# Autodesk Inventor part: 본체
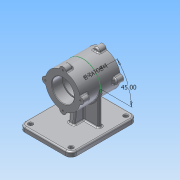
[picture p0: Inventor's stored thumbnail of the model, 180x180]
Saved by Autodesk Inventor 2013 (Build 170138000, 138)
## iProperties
Created: 2015-12
Part Number: 본체
Material: 알루미늄 6061
Document SubType Name: Modeling
Designer: user-11
Density: 2.71 g/cm^3
Mass: 1174.47 g
Surface Area: 817.122 cm^2
Volume: 433.385 cm^3
Author: user-11
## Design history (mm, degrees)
sketch "스케치1"
  geometry: C1 r 37 at (0, 0); 1 further point
  constraints: 1 centre point, 1 coincident
  dimensions: "d0" = 74 diameter of C1
extrude "돌출1" new body sketch "스케치1" stored distance "d2" = 85; taper "d3" = 0 deg
sketch "스케치2"
  geometry: C1 r 7 at (0, 37); 1 further point
  constraints: 2 vertical alignment, 1 centre point, 1 other
  dimensions: "d4" = 14 diameter of C1
extrude "돌출2" join sketch "스케치2" distance "d7" = 15; taper "d8" = 0 deg
node "작업 평면1"
node "작업 평면2"
sketch "스케치4"
  geometry: L1 (55, 80)-(-55, 80); L2 (-55, 80)-(-55, -60); L3 (-55, -60)-(55, -60); L4 (55, -60)-(55, 80); 2 further points
  constraints: 8 end point, 2 parallel, 1 horizontal, 1 midpoint, 1 perpendicular, 1 vertical alignment
  dimensions: "d14" = 55 distance from line of L4 point (0, 0); "d15" = 80 distance from line of L1 point (0, 0); "d16" = 140 distance of L3.end L1.start
extrude "돌출4" join sketch "스케치4" distance "d17" = 10; taper "d18" = 0 deg
sketch "스케치5"
  geometry: L1 (-55, -80)-(55, -80) reference; L2 (-55, 60)-(-55, -80) reference; C1 r 4 at (-43, -68); 1 further point
  constraints: 1 centre point
  dimensions: "d19" = 12 distance from line of L1 C1.centre; "d20" = 12 distance from line of C1.centre L2; "d21" = 8 diameter of C1
extrude "돌출5" cut sketch "스케치5" distance "d22" = 10; taper "d23" = 0 deg
sketch "스케치7"
  geometry: L1 (-55, -80)-(55, -80) reference; L2 (55, 60)-(-55, 60) reference; L3 (-6, 4)-(6, 4); L4 (6, 4)-(6, -4); L5 (6, -4)-(-6, -4); L6 (-6, -4)-(-6, 4); 3 further points
  constraints: 8 end point, 2 midpoint, 2 parallel, 1 horizontal, 1 perpendicular, 1 vertical alignment
  dimensions: "d30" = 8 distance of L5.end L3.start; "d32" = 12 distance of L3.start L3.end; "d33" = 84 distance between parallel lines of L1 L3
extrude "돌출6" join sketch "스케치7" stored distance "d34" = 10; taper "d35" = 0 deg
sketch "스케치8"
  geometry: L1 (-70, -60)-(-70, 80) reference; L2 (-37, -42.5)-(-37, 42.5) reference; L3 (-70, -25)-(-37, -20.948); L4 (-36.51, -4)-(-36.51, 4) reference; L5 (-70, -4)-(-36.51, -4) reference; L6 (-70, 4)-(-70, -4) reference; L7 (-70, 4)-(-36.51, 4) reference; 1 further point
  constraints: 2 end point, 2 point on line
  dimensions: "d36" = 29 distance of L3.start L6.start; "d37" = 97 deg angle of L3 L1
feature "리브1" sketch "스케치8" dims "d38" = 1, "d39" = 12, "d40" = 0, "d41" = 0, "d42" = 1, "d43" = 1
node "작업 평면3"
sketch "스케치9"
  geometry: L1 (-6, -70)-(6, -70) reference; L2 (55, -70)-(-55, -70) reference; L3 (-37, -70)-(-37, 0); 2 further points
  constraints: 2 end point, 1 horizontal alignment, 1 point on line, 1 vertical, 1 other
  dimensions: "d45" = 37 distance from line of L3 point (0, 0)
feature "리브2" sketch "스케치9" dims "d46" = 1, "d47" = 8, "d48" = 0, "d49" = 0, "d50" = 1, "d51" = 1
sketch "스케치10"
  geometry: C1 r 23.5 at (0, 0); A1 r 37 centre (0, 0) between (-6.969, 36.338) and (6.969, 36.338) reference
  constraints: 1 centre point, 1 coincident
  dimensions: "d52" = 47 diameter of C1
extrude "돌출7" cut sketch "스케치10" distance "d54" = 22; taper "d55" = 0 deg
sketch "스케치11"
  geometry: C1 r 23.5 at (0, 0) reference; C2 r 21 at (0, 0)
  constraints: 1 centre point, 1 coincident
  dimensions: "d56" = 42 diameter of C2
extrude "돌출8" cut sketch "스케치11" distance "d58" = 41; taper "d59" = 0 deg
sketch "스케치12"
  geometry: L1 (37, 0)-(0, 0); L2 (0, 0)-(26.163, 26.163); A1 r 37 centre (0, 0) between (37, 0) and (26.163, 26.163) reference; 1 further point
  constraints: 4 end point, 2 point on circle, 1 horizontal
  dimensions: "d60" = 45 deg angle of L2 L1
node "작업 평면4"
sketch "스케치13"
  geometry: 2 further points
  constraints: 1 coincident, 1 other
feature "엠보싱1" sketch "스케치13" dims "d0" = 74, "d61" = 0.5, "d62" = 0
fillet "모깎기1" dims "d63" = 3
fillet "모깎기2" dims "d64" = 3
fillet "모깎기3" dims "d65" = 12
fillet "모깎기4" dims "d66" = 3
fillet "모깎기5" dims "d67" = 3
fillet "모깎기6" dims "d68" = 3
fillet "모깎기7" dims "d69" = 3
fillet "모깎기8" dims "d70" = 0.3
chamfer "모따기1" distance "d71" = 1; stored, may be unused: second distance "d72" = 2, angle "d73" = 45 deg
sketch "스케치14"
  geometry: A1 r 7 centre (0, 37) between (6.889, 38.239) and (-6.889, 38.239) reference; 1 further point
  constraints: 1 coincident
hole "구멍1" sketch "스케치14" at (0, 37) diameter "d74" = 3.242; stored, may be unused: countersink angle "d78" = 90 deg, drill point angle "d80" = 118 deg; dims "d75" = 9, "d76" = 4, "d77" = 2, "d79" = 11
chamfer "모따기2" distance "d84" = 1; stored, may be unused: second distance "d85" = 2, angle "d86" = 45 deg
node "솔리드1"
pattern_linear "직사각형 패턴1" dims "d26" = 86, "d29" = 116
mirror "대칭1"
mirror "대칭2"
mirror "대칭3"
pattern_circular "원형 패턴1" dims "d82" = 360 deg
mirror "대칭4"
node "투영된 루프1"
other parameters: "d9" = 0, "d44" = 0
